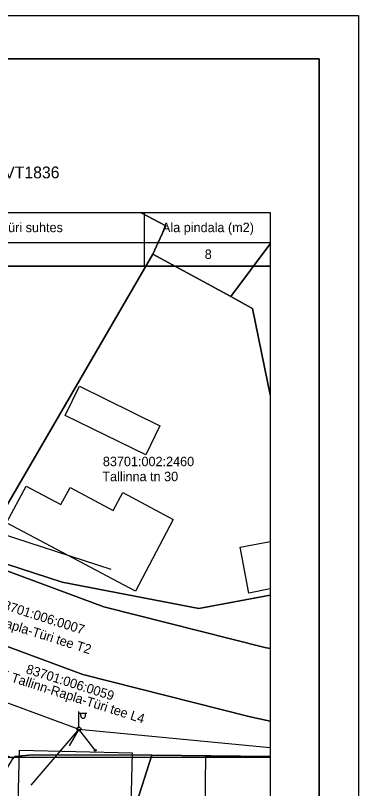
# Model space of a CAD drawing. Extents: x 581758 to 581863, y 6519692 to 6519840.
# Drawn here: x 581818.9 to 581862.5, y 6519742 to 6519840.1 of the extents above; entities that cross this region are included whole.
import ezdxf

# ---------------------------------------------------------------- set-up
doc = ezdxf.new("R2010")
doc.units = 0
for name, color, linetype in [('Hoone Elu- või ühiskondlik hoone', 7, 'Continuous'), ('Hoone Kõrval- või tootmishoone', 7, 'Continuous'), ('MPOHULIIN', 7, 'Continuous'), ('PIIR', 7, 'Continuous'), ('POST', 7, 'Continuous'), ('proj_trass_kliendiliin ohuliin', 7, 'Continuous'), ('proj_trass_multitoru ohuliinil', 7, 'Continuous'), ('VORMISTUS', 7, 'Continuous')]:
    doc.layers.add(name, color=color, linetype=linetype)

msp = doc.modelspace()

# ---------------------------------------------------------------- linework, layer by layer
at = {"layer": 'Hoone Elu- või ühiskondlik hoone'}
for points in [[(581820.278, 6519780.362), (581824.714, 6519778.005), (581825.87, 6519780.181), (581831.369, 6519777.267), (581832.569, 6519779.519), (581838.994, 6519776.116), (581834.183, 6519767.017), (581817.805, 6519775.691)], [(581833.758, 6519746.511), (581833.573, 6519738.195), (581819.242, 6519738.513), (581819.434, 6519746.834)]]:
    msp.add_lwpolyline(points, close=True, dxfattribs=at)
msp.add_lwpolyline([(581851.299, 6519735.432), (581843.022, 6519735.524), (581843.135, 6519746.116), (581851.299, 6519746.02)], dxfattribs=at)
at = {"layer": 'Hoone Kõrval- või tootmishoone'}
msp.add_lwpolyline([(581837.305, 6519787.987), (581835.503, 6519784.308), (581825.26, 6519789.329), (581827.07, 6519793.016)], close=True, dxfattribs=at)
msp.add_lwpolyline([(581851.299, 6519767.293), (581848.576, 6519766.782), (581847.488, 6519772.604), (581851.299, 6519773.313)], dxfattribs=at)
at = {"layer": 'MPOHULIIN'}
msp.add_line((581826.999, 6519749.516), (581825.778, 6519747.405), dxfattribs=at)
msp.add_lwpolyline([(581809.431, 6519755.967), (581826.999, 6519749.516), (581851.299, 6519747.177)], dxfattribs=at)
at = {"layer": 'PIIR'}
for points in [[(581834.823, 6519815.079), (581838.04, 6519813.4), (581836.4, 6519809.77), (581814.17, 6519771.63), (581782.73, 6519790.33), (581796.078, 6519815.079)], [(581851.299, 6519811.086), (581846.31, 6519804.4), (581836.4, 6519809.77), (581838.04, 6519813.4), (581834.823, 6519815.079)], [(581851.299, 6519791.941), (581849.05, 6519802.9), (581848.05, 6519803.45), (581846.31, 6519804.4), (581851.299, 6519811.086)], [(581851.299, 6519766.524), (581842.25, 6519764.8), (581824.87, 6519768.18), (581814.17, 6519771.63), (581836.4, 6519809.77), (581846.31, 6519804.4), (581848.05, 6519803.45), (581849.05, 6519802.9), (581851.299, 6519791.941)], [(581768.79, 6519798.922), (581782.73, 6519790.33), (581814.17, 6519771.63), (581824.87, 6519768.18), (581842.25, 6519764.8), (581851.299, 6519766.524)], [(581768.79, 6519795.896), (581790.19, 6519783.08), (581813.81, 6519771.08), (581830.15, 6519765.04), (581850.62, 6519759.88), (581851.299, 6519759.735)], [(581851.299, 6519759.735), (581850.62, 6519759.88), (581830.15, 6519765.04), (581813.81, 6519771.08), (581790.19, 6519783.08), (581768.79, 6519795.896)], [(581768.79, 6519785.369), (581785.83, 6519775.2), (581810.2, 6519762.82), (581827.48, 6519756.43), (581848.58, 6519751.11), (581851.299, 6519750.53)], [(581851.299, 6519750.53), (581848.58, 6519751.11), (581827.48, 6519756.43), (581810.2, 6519762.82), (581785.83, 6519775.2), (581768.79, 6519785.369)], [(581851.299, 6519746.03), (581836.27, 6519746.21), (581821.06, 6519746.26), (581818.91, 6519746.03), (581818.63, 6519745.83), (581797.39, 6519753.15), (581799.19, 6519762.22), (581792.48, 6519765.15), (581788.51, 6519764.43), (581768.79, 6519775.028)], [(581812.581, 6519710.029), (581799.14, 6519713.16), (581818.63, 6519745.83), (581818.91, 6519746.03), (581821.06, 6519746.26), (581836.27, 6519746.21), (581828.64, 6519722.33), (581824.71, 6519710.029)], [(581851.299, 6519718.992), (581850.1, 6519715.45), (581828.64, 6519722.33), (581836.27, 6519746.21), (581851.299, 6519746.03)]]:
    msp.add_lwpolyline(points, dxfattribs=at)
at = {"layer": 'POST'}
for p, q in [((581826.999, 6519749.766), (581826.999, 6519751.766)), ((581826.999, 6519751.516), (581827.999, 6519751.516)), ((581827.226, 6519751.195), (581827.226, 6519751.516)), ((581827.839, 6519751.195), (581827.839, 6519751.516)), ((581826.999, 6519749.516), (581826.999, 6519749.516))]:
    msp.add_line(p, q, dxfattribs=at)
msp.add_lwpolyline([(581829.074, 6519746.841), (581826.999, 6519749.516)], dxfattribs=at)
for centre, radius in [((581826.999, 6519749.516), 0.25), ((581829.074, 6519746.841), 0.125), ((581829.074, 6519746.841), 0.105), ((581829.074, 6519746.841), 0.0851), ((581829.074, 6519746.841), 0.0651), ((581829.074, 6519746.841), 0.0451), ((581829.074, 6519746.841), 0.0251), ((581829.074, 6519746.841), 0.00511)]:
    msp.add_circle(centre, radius, dxfattribs=at)
msp.add_arc((581827.532, 6519751.195), 0.306, 180, 0, dxfattribs=at)
at = {"layer": 'proj_trass_kliendiliin ohuliin'}
for points in [[(581799.645, 6519779.996), (581831.052, 6519769.813)], [(581826.999, 6519749.516), (581820.907, 6519742.411)]]:
    msp.add_lwpolyline(points, dxfattribs=at)
at = {"layer": 'proj_trass_multitoru ohuliinil'}
msp.add_lwpolyline([(581801.81, 6519758.765), (581826.999, 6519749.516), (581851.299, 6519747.177)], dxfattribs=at)
at = {"layer": 'VORMISTUS'}
for p, q in [((581835.29, 6519815.079), (581835.29, 6519808.279)), ((581768.79, 6519811.279), (581851.29, 6519811.279)), ((581768.79, 6519808.279), (581851.29, 6519808.279))]:
    msp.add_line(p, q, dxfattribs=at)
for points in [[(581757.54, 6519840.079), (581862.54, 6519840.079), (581862.54, 6519691.579), (581757.54, 6519691.579)], [(581762.54, 6519697.079), (581857.54, 6519697.079), (581857.54, 6519834.579), (581762.54, 6519834.579)], [(581762.54, 6519834.579), (581857.54, 6519834.579), (581857.54, 6519697.079), (581762.54, 6519697.079)], [(581768.79, 6519815.079), (581851.29, 6519815.079), (581851.29, 6519808.279), (581768.79, 6519808.279)], [(581851.29, 6519710.079), (581768.79, 6519710.079), (581768.79, 6519815.079), (581851.29, 6519815.079)]]:
    msp.add_lwpolyline(points, close=True, dxfattribs=at)
msp.add_lwpolyline([(581851.299, 6519745.924), (581768.79, 6519745.924)], dxfattribs=at)

# ---------------------------------------------------------------- texts
at = {"layer": 'PIIR'}
for s, p in [('83701:002:2460', (581830.045, 6519782.878)), ('Tallinna tn 30', (581829.982, 6519780.973))]:
    msp.add_text(s, height=1.2, dxfattribs=at).set_placement(p)
for s, rotation, p in [('15 Tallinn-Rapla-Türi tee T2', 342.522, (581809.294, 6519765.012)), ('83701:006:0007', 342.522, (581816.431, 6519764.997)), ('15 Tallinn-Rapla-Türi tee L4', 342.41466, (581816.171, 6519756.217)), ('83701:006:0059', 342.41466, (581820.188, 6519756.623))]:
    msp.add_text(s, height=1.2, rotation=rotation, dxfattribs=at).set_placement(p)
at = {"layer": 'VORMISTUS'}
msp.add_text('Kirjanurk OÜ töö nr 8500P/Enefit Connect OÜ tellimus VT1836', height=1.5, rotation=360, dxfattribs=at).set_placement((581768.787, 6519819.409))
for s, p in [('Asukoht riigitee 15 Tallinn-Rapla-Türi suhtes ', (581793.391, 6519812.579)), ('Ala pindala (m2)', (581837.561, 6519812.579)), ('8', (581842.99, 6519809.179))]:
    msp.add_text(s, height=1.2, dxfattribs=at).set_placement(p)

doc.saveas('drawing.dxf')
